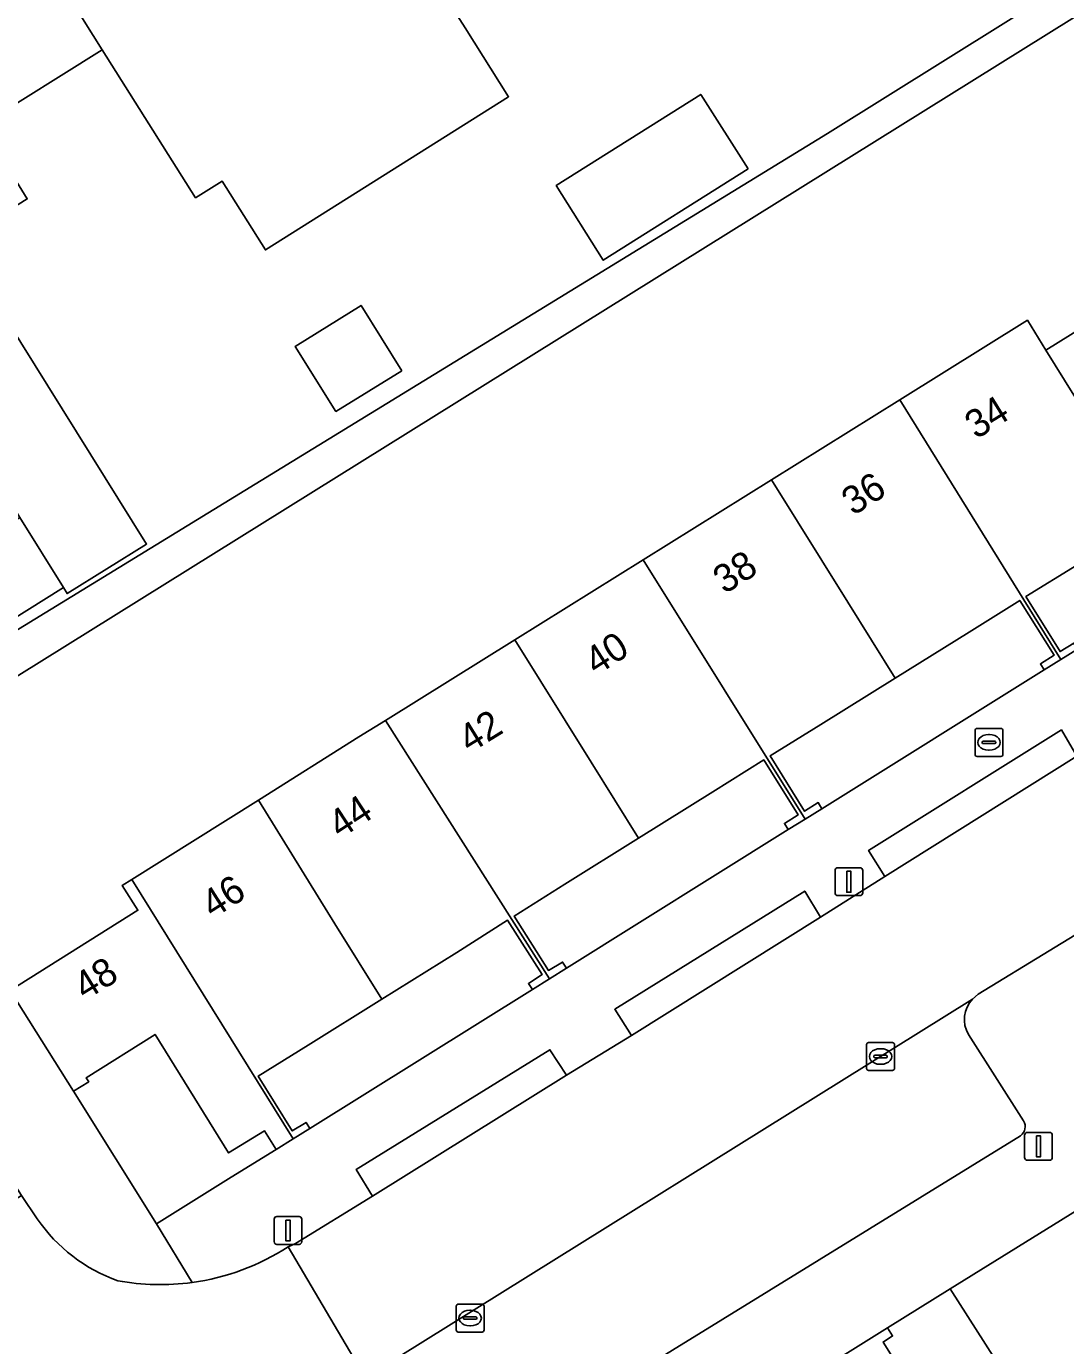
# Model space of a CAD drawing. Extents: x 159352 to 160617, y 385888 to 387323.
# Drawn here: x 159757.01 to 159794.23, y 386028.96 to 386076.22 of the extents above; entities that cross this region are included whole.
import ezdxf

# ---------------------------------------------------------------- set-up
doc = ezdxf.new("R2010")
doc.units = 0
for name, color, linetype in [('IMGEO_Brandkraan', 7, 'Continuous'), ('IMGEO_Erf', 7, 'Continuous'), ('IMGEO_Kolk', 7, 'Continuous'), ('IMGEO_Lichtmast', 7, 'Continuous'), ('IMGEO_Pand', 7, 'Continuous'), ('IMGEO_Pand_nummerreeks', 7, 'Continuous'), ('IMGEO_Pand_overbouw', 7, 'Continuous'), ('IMGEO_Parkeervlak_open', 7, 'Continuous'), ('IMGEO_Rijbaan_lokaal_open', 7, 'Continuous'), ('IMGEO_Voetpad_open', 7, 'Continuous')]:
    doc.layers.add(name, color=color, linetype=linetype)

msp = doc.modelspace()

# ---------------------------------------------------------------- linework, layer by layer
at = {"layer": 'IMGEO_Brandkraan'}
for p, q in [((159790.983, 386050.143), (159790.983, 386050.995)), ((159791.058, 386051.069), (159791.91, 386051.069)), ((159791.984, 386050.995), (159791.984, 386050.143)), ((159791.242, 386050.563), (159791.242, 386050.575)), ((159791.68, 386050.526), (159791.282, 386050.526)), ((159791.285, 386050.612), (159791.683, 386050.612)), ((159791.471, 386050.849), (159791.496, 386050.849)), ((159791.726, 386050.575), (159791.726, 386050.563)), ((159791.91, 386050.069), (159791.058, 386050.069)), ((159791.494, 386050.289), (159791.469, 386050.289))]:
    msp.add_line(p, q, dxfattribs=at)
for points in [[(159790.983, 386050.143), (159790.983, 386050.995)], [(159791.058, 386051.069), (159791.91, 386051.069)], [(159791.984, 386050.995), (159791.984, 386050.143)], [(159791.91, 386050.069), (159791.058, 386050.069)]]:
    msp.add_lwpolyline(points, dxfattribs=at)
for centre, radius, start, end in [((159791.06, 386050.993), 0.0765, 91.552, 178.448), ((159791.06, 386050.993), 0.0765, 91.552, 178.448), ((159791.908, 386050.993), 0.0765, 1.552, 88.448), ((159791.908, 386050.993), 0.0765, 1.552, 88.448), ((159791.282, 386050.572), 0.0403, 85.8775, 175.7526), ((159791.279, 386050.562), 0.0366, 178.938, 274.7102), ((159791.683, 386050.569), 0.043, 264.8664, 352.4533), ((159791.687, 386050.574), 0.0386, 1.7309, 96.639), ((159791.06, 386050.145), 0.0765, 181.552, 268.448), ((159791.06, 386050.145), 0.0765, 181.552, 268.448), ((159791.908, 386050.145), 0.0765, 271.552, 358.448), ((159791.908, 386050.145), 0.0765, 271.552, 358.448)]:
    msp.add_arc(centre, radius, start, end, dxfattribs=at)
for centre, major_axis, ratio, start_param, end_param in [((159791.47, 386050.569), (-0.387, 0.002), 0.722429, 4.712389, 7.853982), ((159791.495, 386050.569), (-0.39, 0.002), 0.717154, 1.570796, 4.712389)]:
    msp.add_ellipse(centre, major_axis=major_axis, ratio=ratio, start_param=start_param, end_param=end_param, dxfattribs=at)
at = {"layer": 'IMGEO_Erf'}
for points in [[(159846.595, 386144.231), (159735.083, 386074.392), (159734.716, 386071.987), (159736.771, 386068.736), (159737.062, 386068.923), (159749.045, 386049.918), (159785.705, 386072.384), (159811.147, 386088.283)], [(159862.072, 386118.665), (159751.412, 386049.66), (159756.434, 386041.685), (159761.007, 386044.556), (159760.449, 386045.445), (159760.791, 386045.66), (159765.322, 386048.505), (159768.918, 386050.763), (159769.875, 386051.359), (159774.501, 386054.244), (159779.096, 386057.11), (159783.69, 386059.974), (159788.287, 386062.841), (159792.859, 386065.692), (159793.523, 386064.622), (159798.094, 386067.462)], [(159772.322, 386076.799), (159772.722, 386076.165), (159774.279, 386073.697), (159765.576, 386068.207), (159764.019, 386070.675), (159763.073, 386070.078), (159759.732, 386075.374), (159755.402, 386072.674), (159757.046, 386070.036), (159753.88, 386068.063)], [(159756.304, 386065.712), (159761.317, 386057.675), (159758.472, 386055.901), (159758.341, 386056.112), (159754.393, 386053.65)], [(159828.216, 386026.081), (159832.89, 386028.986), (159833.434, 386029.324), (159830.012, 386034.809), (159829.469, 386034.471), (159822.293, 386030.004), (159818.431, 386036.189), (159817.582, 386035.659), (159811.969, 386044.648), (159804.855, 386040.143), (159801.54, 386038.089), (159790.097, 386030.999), (159787.845, 386029.593), (159788.029, 386029.306), (159787.689, 386029.088), (159794.008, 386018.98)]]:
    msp.add_lwpolyline(points, dxfattribs=at)
for points in [[(159782.859, 386071.11), (159777.673, 386067.839), (159775.986, 386070.513), (159781.165, 386073.78)], [(159770.455, 386063.883), (159768.095, 386062.426), (159766.642, 386064.756), (159768.996, 386066.224)], [(159802.636, 386058.882), (159802.216, 386059.547), (159800.928, 386058.745), (159798.242, 386062.945), (159795.587, 386061.297), (159795.283, 386061.109), (159796.976, 386058.381), (159794.624, 386056.921), (159792.806, 386055.793), (159794.029, 386053.822), (159794.522, 386054.128), (159794.659, 386053.907), (159798.331, 386056.198)], [(159793.465, 386053.166), (159793.328, 386053.38), (159793.816, 386053.693), (159792.586, 386055.653), (159790.772, 386054.523), (159788.122, 386052.871), (159785.467, 386051.216), (159783.647, 386050.082), (159784.88, 386048.104), (159785.368, 386048.413), (159785.498, 386048.195)], [(159784.295, 386047.444), (159784.157, 386047.665), (159784.649, 386047.972), (159783.419, 386049.942), (159781.595, 386048.804), (159778.937, 386047.144), (159776.291, 386045.49), (159774.482, 386044.348), (159775.706, 386042.402), (159776.217, 386042.698), (159776.35, 386042.484)], [(159775.132, 386041.713), (159774.99, 386041.929), (159775.478, 386042.254), (159774.244, 386044.199), (159772.428, 386043.048), (159769.738, 386041.369), (159767.109, 386039.728), (159765.317, 386038.615), (159766.535, 386036.653), (159767.028, 386036.959), (159767.165, 386036.738)], [(159761.674, 386033.329), (159764.352, 386034.991), (159765.962, 386035.991), (159765.538, 386036.658), (159764.257, 386035.863), (159761.62, 386040.107), (159759.159, 386038.558), (159759.248, 386038.413), (159758.7, 386038.075)]]:
    msp.add_lwpolyline(points, close=True, dxfattribs=at)
at = {"layer": 'IMGEO_Kolk'}
for p, q in [((159787.1, 386038.892), (159787.1, 386039.744)), ((159787.175, 386039.818), (159788.027, 386039.818)), ((159788.101, 386039.744), (159788.101, 386038.892)), ((159787.359, 386039.312), (159787.359, 386039.324)), ((159787.797, 386039.275), (159787.399, 386039.275)), ((159787.402, 386039.361), (159787.8, 386039.361)), ((159787.588, 386039.598), (159787.613, 386039.598)), ((159787.843, 386039.324), (159787.843, 386039.312)), ((159788.027, 386038.818), (159787.175, 386038.818)), ((159787.611, 386039.038), (159787.586, 386039.038)), ((159772.403, 386029.521), (159772.403, 386030.373)), ((159772.478, 386030.447), (159773.33, 386030.447)), ((159772.891, 386030.227), (159772.916, 386030.227)), ((159773.404, 386030.373), (159773.404, 386029.521)), ((159772.662, 386029.941), (159772.662, 386029.953)), ((159773.1, 386029.904), (159772.702, 386029.904)), ((159772.705, 386029.99), (159773.103, 386029.99)), ((159773.146, 386029.953), (159773.146, 386029.941)), ((159773.33, 386029.447), (159772.478, 386029.447)), ((159772.914, 386029.667), (159772.889, 386029.667))]:
    msp.add_line(p, q, dxfattribs=at)
for points in [[(159787.1, 386038.892), (159787.1, 386039.744)], [(159787.175, 386039.818), (159788.027, 386039.818)], [(159788.101, 386039.744), (159788.101, 386038.892)], [(159788.027, 386038.818), (159787.175, 386038.818)], [(159772.403, 386029.521), (159772.403, 386030.373)], [(159772.478, 386030.447), (159773.33, 386030.447)], [(159773.404, 386030.373), (159773.404, 386029.521)], [(159773.33, 386029.447), (159772.478, 386029.447)]]:
    msp.add_lwpolyline(points, dxfattribs=at)
for centre, radius, start, end in [((159787.177, 386039.742), 0.0765, 91.552, 178.448), ((159787.177, 386039.742), 0.0765, 91.552, 178.448), ((159788.025, 386039.742), 0.0765, 1.552, 88.448), ((159788.025, 386039.742), 0.0765, 1.552, 88.448), ((159787.399, 386039.321), 0.0403, 85.8775, 175.7526), ((159787.396, 386039.311), 0.0366, 178.938, 274.7102), ((159787.8, 386039.318), 0.043, 264.8664, 352.4533), ((159787.804, 386039.323), 0.0386, 1.7309, 96.639), ((159787.177, 386038.894), 0.0765, 181.552, 268.448), ((159787.177, 386038.894), 0.0765, 181.552, 268.448), ((159788.025, 386038.894), 0.0765, 271.552, 358.448), ((159788.025, 386038.894), 0.0765, 271.552, 358.448), ((159772.48, 386030.371), 0.0765, 91.552, 178.448), ((159772.48, 386030.371), 0.0765, 91.552, 178.448), ((159773.328, 386030.371), 0.0765, 1.552, 88.448), ((159773.328, 386030.371), 0.0765, 1.552, 88.448), ((159772.702, 386029.95), 0.0403, 85.8775, 175.7526), ((159772.699, 386029.94), 0.0366, 178.938, 274.7102), ((159773.103, 386029.947), 0.043, 264.8664, 352.4533), ((159773.107, 386029.952), 0.0386, 1.7309, 96.639), ((159772.48, 386029.523), 0.0765, 181.552, 268.448), ((159772.48, 386029.523), 0.0765, 181.552, 268.448), ((159773.328, 386029.523), 0.0765, 271.552, 358.448), ((159773.328, 386029.523), 0.0765, 271.552, 358.448)]:
    msp.add_arc(centre, radius, start, end, dxfattribs=at)
for centre, major_axis, ratio, start_param, end_param in [((159787.587, 386039.318), (-0.387, 0.002), 0.722429, 4.712389, 7.853982), ((159787.612, 386039.318), (-0.39, 0.002), 0.717154, 1.570796, 4.712389), ((159772.89, 386029.947), (-0.387, 0.002), 0.722429, 4.712389, 7.853982), ((159772.915, 386029.947), (-0.39, 0.002), 0.717154, 1.570796, 4.712389)]:
    msp.add_ellipse(centre, major_axis=major_axis, ratio=ratio, start_param=start_param, end_param=end_param, dxfattribs=at)
at = {"layer": 'IMGEO_Lichtmast'}
for p, q in [((159785.972, 386045.179), (159785.972, 386045.979)), ((159785.972, 386045.979), (159785.972, 386045.179)), ((159786.072, 386046.079), (159786.862, 386046.079)), ((159786.862, 386046.079), (159786.072, 386046.079)), ((159786.962, 386045.979), (159786.962, 386045.179)), ((159786.962, 386045.179), (159786.962, 386045.979)), ((159786.862, 386045.079), (159786.072, 386045.079)), ((159786.072, 386045.079), (159786.862, 386045.079)), ((159792.761, 386035.7), (159792.761, 386036.5)), ((159792.761, 386036.5), (159792.761, 386035.7)), ((159792.861, 386036.6), (159793.651, 386036.6)), ((159793.651, 386036.6), (159792.861, 386036.6)), ((159793.751, 386036.5), (159793.751, 386035.7)), ((159793.751, 386035.7), (159793.751, 386036.5)), ((159793.651, 386035.6), (159792.861, 386035.6)), ((159792.861, 386035.6), (159793.651, 386035.6)), ((159765.986, 386033.586), (159766.776, 386033.586)), ((159766.776, 386033.586), (159765.986, 386033.586)), ((159765.886, 386032.686), (159765.886, 386033.486)), ((159765.886, 386033.486), (159765.886, 386032.686)), ((159766.876, 386033.486), (159766.876, 386032.686)), ((159766.876, 386032.686), (159766.876, 386033.486)), ((159766.776, 386032.586), (159765.986, 386032.586)), ((159765.986, 386032.586), (159766.776, 386032.586))]:
    msp.add_line(p, q, dxfattribs=at)
for points in [[(159786.392, 386045.954), (159786.542, 386045.954), (159786.542, 386045.204), (159786.392, 386045.204), (159786.392, 386045.954)], [(159793.181, 386036.475), (159793.331, 386036.475), (159793.331, 386035.725), (159793.181, 386035.725), (159793.181, 386036.475)], [(159766.306, 386033.461), (159766.456, 386033.461), (159766.456, 386032.711), (159766.306, 386032.711), (159766.306, 386033.461)]]:
    msp.add_lwpolyline(points, dxfattribs=at)
for centre, start, end in [((159786.072, 386045.979), 90, 180), ((159786.072, 386045.979), 90, 180), ((159786.862, 386045.979), 0, 90), ((159786.862, 386045.979), 360, 90), ((159786.072, 386045.179), 180, 270), ((159786.072, 386045.179), 180, 270), ((159786.862, 386045.179), 270, 0), ((159786.862, 386045.179), 270, 0), ((159792.861, 386036.5), 90, 180), ((159792.861, 386036.5), 90, 180), ((159793.651, 386036.5), 0, 90), ((159793.651, 386036.5), 360, 90), ((159792.861, 386035.7), 180, 270), ((159792.861, 386035.7), 180, 270), ((159793.651, 386035.7), 270, 0), ((159793.651, 386035.7), 270, 0), ((159765.986, 386033.486), 90, 180), ((159765.986, 386033.486), 90, 180), ((159766.776, 386033.486), 0, 90), ((159766.776, 386033.486), 360, 90), ((159765.986, 386032.686), 180, 270), ((159765.986, 386032.686), 180, 270), ((159766.776, 386032.686), 270, 0), ((159766.776, 386032.686), 270, 0)]:
    msp.add_arc(centre, 0.1, start, end, dxfattribs=at)
at = {"layer": 'IMGEO_Pand'}
for points in [[(159766.64, 386085.875), (159761.234, 386082.494), (159761.492, 386082.086), (159757.19, 386079.405), (159758.698, 386077.014), (159759.732, 386075.374), (159763.073, 386070.078), (159764.019, 386070.675), (159765.576, 386068.207), (159774.279, 386073.697), (159772.722, 386076.165), (159772.322, 386076.799)], [(159759.732, 386075.374), (159758.698, 386077.014), (159757.19, 386079.405), (159752.882, 386076.718), (159751.559, 386078.84), (159746.435, 386075.635), (159750.274, 386069.478), (159751.919, 386066.841), (159753.793, 386063.836), (159755.753, 386065.058), (159755.614, 386065.282), (159753.88, 386068.063), (159757.046, 386070.036), (159755.402, 386072.674)], [(159782.859, 386071.11), (159781.165, 386073.78), (159775.986, 386070.513), (159777.673, 386067.839)], [(159795.587, 386061.297), (159798.242, 386062.945), (159800.928, 386058.745), (159802.216, 386059.547), (159802.636, 386058.882), (159803.233, 386059.258), (159798.094, 386067.462), (159793.523, 386064.622)], [(159770.455, 386063.883), (159768.996, 386066.224), (159766.642, 386064.756), (159768.095, 386062.426)], [(159756.304, 386065.712), (159755.614, 386065.282), (159755.753, 386065.058), (159753.793, 386063.836), (159753.599, 386063.715), (159756.774, 386058.623), (159758.341, 386056.112), (159758.472, 386055.901), (159761.317, 386057.675)], [(159794.624, 386056.921), (159796.976, 386058.381), (159795.283, 386061.109), (159795.587, 386061.297), (159793.523, 386064.622), (159792.859, 386065.692), (159788.287, 386062.841), (159794.062, 386053.536), (159794.659, 386053.907), (159794.522, 386054.128), (159794.029, 386053.822), (159792.806, 386055.793)], [(159788.287, 386062.841), (159783.69, 386059.974), (159786.424, 386055.592), (159788.122, 386052.871), (159790.772, 386054.523), (159792.586, 386055.653), (159793.816, 386053.693), (159793.328, 386053.38), (159793.465, 386053.166), (159794.062, 386053.536)], [(159786.424, 386055.592), (159783.69, 386059.974), (159779.096, 386057.11), (159784.896, 386047.82), (159785.498, 386048.195), (159785.368, 386048.413), (159784.88, 386048.104), (159783.647, 386050.082), (159785.467, 386051.216), (159788.122, 386052.871)], [(159756.774, 386058.623), (159752.827, 386056.162), (159754.393, 386053.65), (159758.341, 386056.112)], [(159779.096, 386057.11), (159774.501, 386054.244), (159777.242, 386049.857), (159778.937, 386047.144), (159781.595, 386048.804), (159783.419, 386049.942), (159784.649, 386047.972), (159784.157, 386047.665), (159784.295, 386047.444), (159784.896, 386047.82)], [(159774.501, 386054.244), (159769.875, 386051.359), (159775.741, 386042.098), (159776.35, 386042.484), (159776.217, 386042.698), (159775.706, 386042.402), (159774.482, 386044.348), (159776.291, 386045.49), (159778.937, 386047.144), (159777.242, 386049.857)], [(159769.875, 386051.359), (159768.918, 386050.763), (159765.322, 386048.505), (159768.064, 386044.074), (159769.738, 386041.369), (159772.428, 386043.048), (159774.244, 386044.199), (159775.478, 386042.254), (159774.99, 386041.929), (159775.132, 386041.713), (159775.741, 386042.098)], [(159767.109, 386039.728), (159769.738, 386041.369), (159768.064, 386044.074), (159765.322, 386048.505), (159760.791, 386045.66), (159766.564, 386036.364), (159767.165, 386036.738), (159767.028, 386036.959), (159766.535, 386036.653), (159765.317, 386038.615)], [(159760.791, 386045.66), (159760.449, 386045.445), (159761.007, 386044.556), (159756.434, 386041.685), (159758.7, 386038.075), (159759.248, 386038.413), (159759.159, 386038.558), (159761.62, 386040.107), (159764.257, 386035.863), (159765.538, 386036.658), (159765.962, 386035.991), (159766.564, 386036.364)], [(159770.784, 386018.94), (159781.076, 386002.383), (159800.515, 386014.52), (159796.689, 386020.663), (159794.008, 386018.98), (159787.689, 386029.088), (159788.029, 386029.306), (159787.845, 386029.593)]]:
    msp.add_lwpolyline(points, close=True, dxfattribs=at)
at = {"layer": 'IMGEO_Pand_overbouw'}
for points in [[(159758.7, 386038.075), (159761.674, 386033.329), (159764.352, 386034.991), (159765.962, 386035.991), (159765.538, 386036.658), (159764.257, 386035.863), (159761.62, 386040.107), (159759.159, 386038.558), (159759.248, 386038.413)], [(159790.097, 386030.999), (159787.845, 386029.593), (159788.029, 386029.306), (159787.689, 386029.088), (159794.008, 386018.98), (159796.694, 386020.655)]]:
    msp.add_lwpolyline(points, close=True, dxfattribs=at)
at = {"layer": 'IMGEO_Parkeervlak_open'}
for points in [[(159790.897, 386041.373), (159769.372, 386027.952)], [(159792.722, 386037.015), (159790.755, 386040.107)], [(159772.944, 386024.359), (159792.613, 386036.48)]]:
    msp.add_lwpolyline(points, dxfattribs=at)
for centre, radius, start, end in [((159791.631, 386040.65), 1.031, 135.4241, 211.7764), ((159792.381, 386036.806), 0.4, 305.436, 31.5325)]:
    msp.add_arc(centre, radius, start, end, dxfattribs=at)
at = {"layer": 'IMGEO_Rijbaan_lokaal_open'}
msp.add_lwpolyline([(159802.59, 386048.648), (159808.598, 386052.376), (159808.818, 386052.536), (159805.965, 386057.175), (159803.833, 386055.808), (159796.924, 386051.501), (159794.635, 386050.078), (159787.755, 386045.761), (159785.455, 386044.311), (159778.687, 386040.071), (159776.353, 386038.645), (159769.407, 386034.309), (159766.65, 386032.618), (159766.391, 386032.505), (159769.13, 386027.84), (159769.372, 386027.952), (159790.897, 386041.373), (159791.097, 386041.553), (159796.184, 386044.657), (159798.338, 386045.971)], close=True, dxfattribs=at)
for points in [[(159757.402, 386033.5), (159756.838, 386034.337), (159752.658, 386031.759), (159762.791, 386015.603), (159766.892, 386018.124), (159766.34, 386019.01)], [(159769.13, 386027.84), (159766.391, 386032.505)]]:
    msp.add_lwpolyline(points, dxfattribs=at)
for centre, radius, start, end in [((159762.267, 386036.85), 5.907, 214.5533, 250.4477), ((159761.802, 386039.568), 8.423, 277.8085, 303.0153), ((159761.809, 386039.56), 8.414, 259.6008, 277.7679)]:
    msp.add_arc(centre, radius, start, end, dxfattribs=at)
at = {"layer": 'IMGEO_Voetpad_open'}
for points in [[(159862.072, 386118.665), (159863.515, 386119.625), (159862.703, 386120.84), (159858.735, 386118.451), (159853.141, 386114.986), (159846.534, 386111.027), (159843.253, 386109.048), (159833.831, 386102.938), (159833.908, 386102.815), (159828.655, 386099.532), (159813.439, 386089.716), (159811.147, 386088.283), (159785.705, 386072.384), (159749.045, 386049.918), (159749.859, 386048.628), (159751.412, 386049.66)], [(159787.755, 386045.761), (159794.635, 386050.078), (159794.077, 386051.016), (159787.173, 386046.697)], [(159778.687, 386040.071), (159785.455, 386044.311), (159784.888, 386045.245), (159778.082, 386041.011)], [(159776.353, 386038.645), (159775.76, 386039.558), (159768.82, 386035.27), (159769.407, 386034.309)]]:
    msp.add_lwpolyline(points, close=True, dxfattribs=at)
for points in [[(159762.946, 386031.223), (159761.674, 386033.329), (159758.7, 386038.075), (159756.434, 386041.685), (159751.412, 386049.66), (159749.859, 386048.628), (159749.045, 386049.918), (159737.062, 386068.923)], [(159794.659, 386053.907), (159794.062, 386053.536), (159793.465, 386053.166), (159785.498, 386048.195), (159784.896, 386047.82), (159784.295, 386047.444), (159776.35, 386042.484), (159775.741, 386042.098), (159775.132, 386041.713), (159767.165, 386036.738), (159766.564, 386036.364), (159765.962, 386035.991), (159764.352, 386034.991), (159761.674, 386033.329), (159762.946, 386031.223)], [(159768.82, 386035.27), (159775.76, 386039.558), (159776.353, 386038.645), (159778.687, 386040.071), (159778.082, 386041.011), (159784.888, 386045.245), (159785.455, 386044.311), (159787.755, 386045.761), (159787.173, 386046.697), (159794.077, 386051.016), (159794.635, 386050.078)], [(159802.59, 386048.648), (159798.338, 386045.971), (159796.184, 386044.657), (159791.097, 386041.553), (159790.897, 386041.373)], [(159766.532, 386025.622), (159770.784, 386018.94), (159787.845, 386029.593), (159790.097, 386030.999), (159801.54, 386038.089), (159804.855, 386040.143), (159811.969, 386044.648)], [(159790.755, 386040.107), (159792.722, 386037.015)], [(159755.487, 386036.469), (159756.838, 386034.337), (159757.402, 386033.5)], [(159792.613, 386036.48), (159772.944, 386024.359)], [(159766.391, 386032.505), (159766.65, 386032.618), (159769.407, 386034.309), (159768.82, 386035.27)]]:
    msp.add_lwpolyline(points, dxfattribs=at)
for centre, radius, start, end in [((159791.631, 386040.65), 1.031, 135.4241, 211.7764), ((159792.381, 386036.806), 0.4, 305.436, 31.5325), ((159762.267, 386036.85), 5.907, 214.5533, 250.4477), ((159761.802, 386039.568), 8.423, 277.8085, 303.0153), ((159761.809, 386039.56), 8.414, 259.6008, 277.7679)]:
    msp.add_arc(centre, radius, start, end, dxfattribs=at)

# ---------------------------------------------------------------- texts
at = {"layer": 'IMGEO_Pand_nummerreeks'}
for s, rotation, p in [('34', 31.8966, (159791.026, 386061.409)), ('36', 32.2976, (159786.62, 386058.669)), ('38', 32.2976, (159782.016, 386055.862)), ('40', 32.7216, (159777.42, 386052.945)), ('42', 31.6387, (159772.886, 386050.162)), ('44', 33.2717, (159768.249, 386047.097)), ('46', 32.5898, (159763.693, 386044.238)), ('48', 31.7169, (159759.115, 386041.305))]:
    msp.add_text(s, height=1, rotation=rotation, dxfattribs=at).set_placement(p)

doc.saveas('drawing.dxf')
